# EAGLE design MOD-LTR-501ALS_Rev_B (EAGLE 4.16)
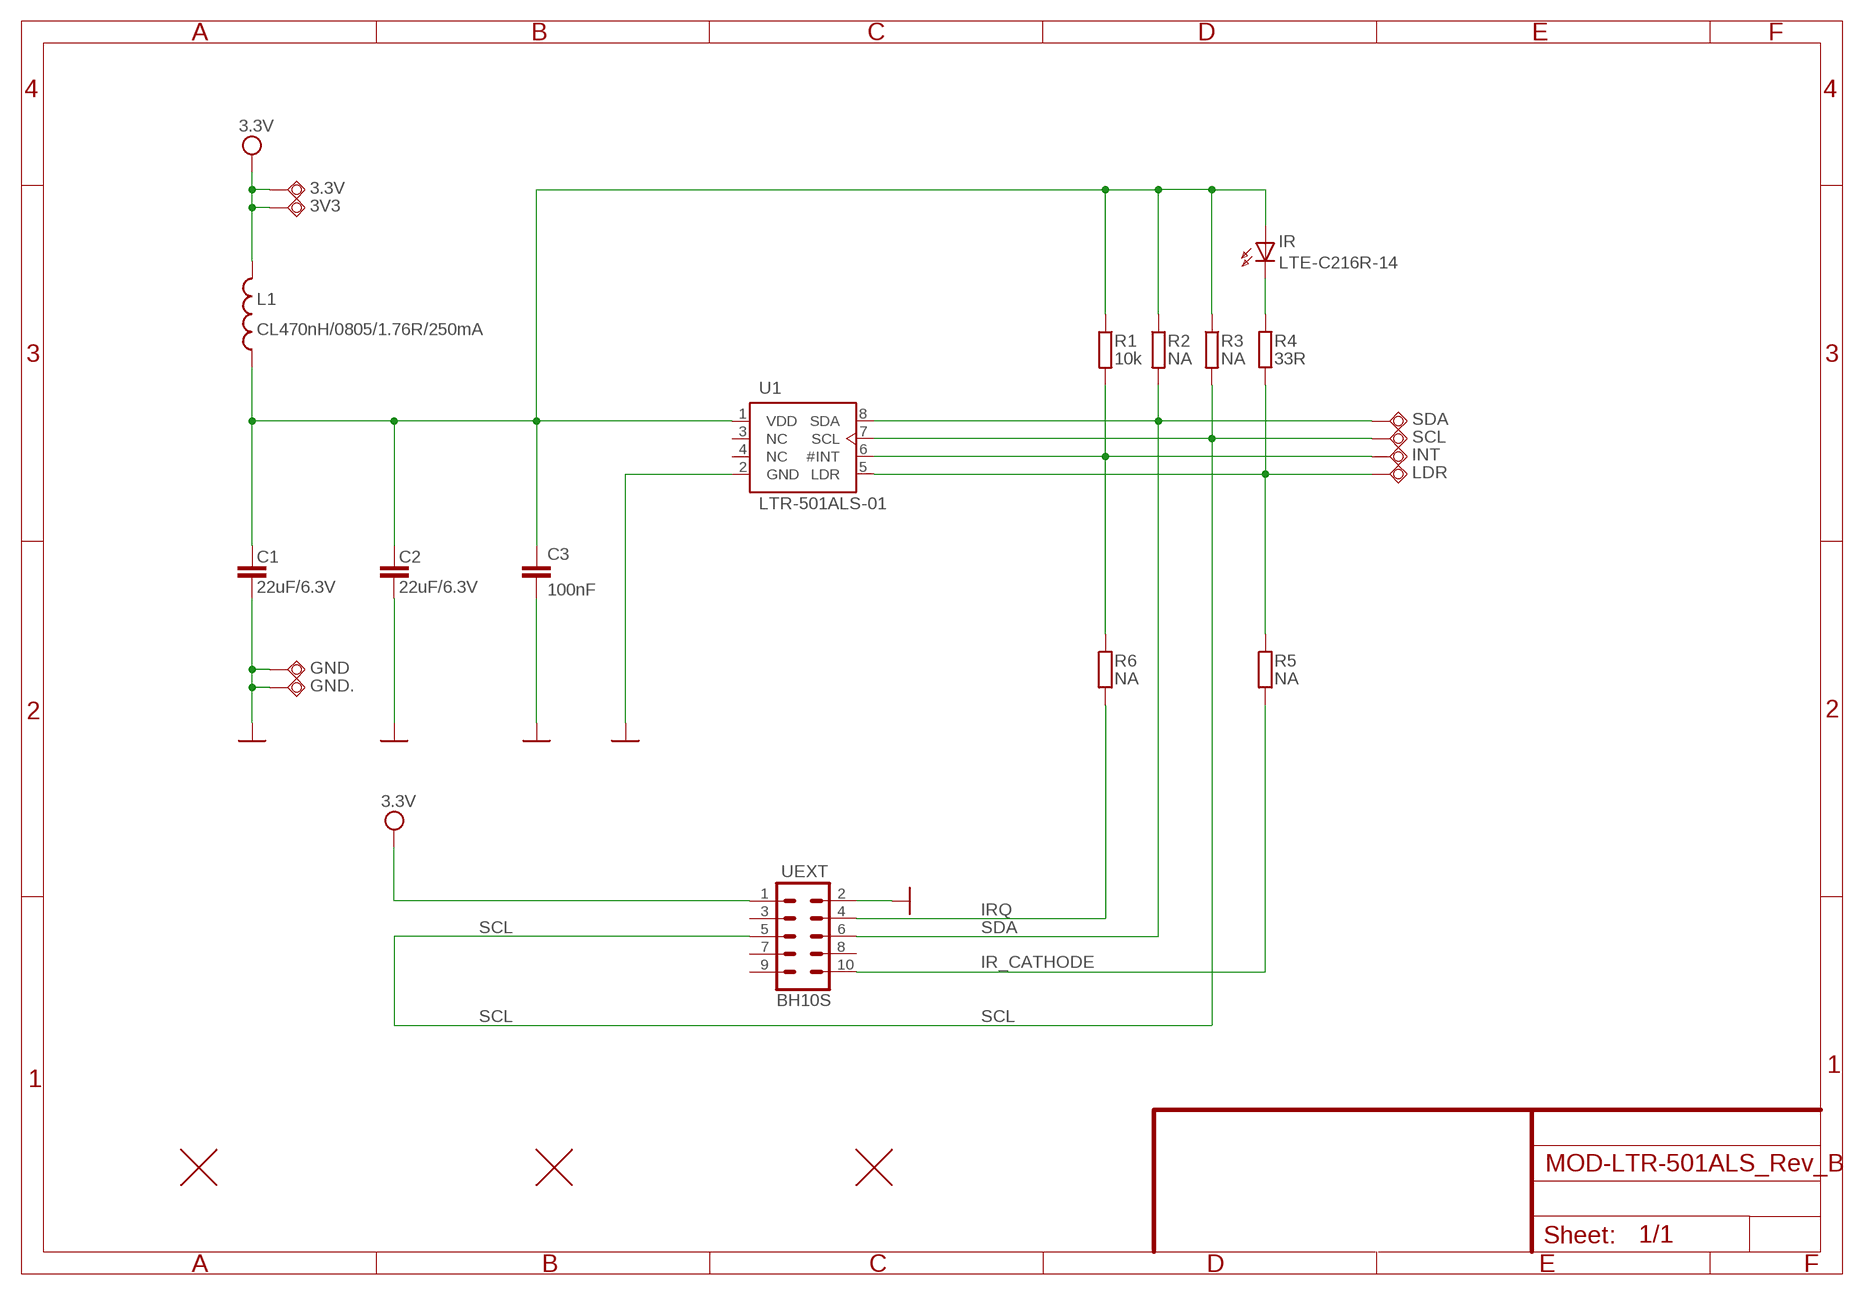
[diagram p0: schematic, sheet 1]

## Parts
3.3V  TESTPAD3  [TEST_PAD40/70/SQUARE]
3V3  TESTPAD3  [TEST_PAD40/70/SQUARE]
C1  22uF/6.3V  C-EUC0603_DWS  [C0603_DWS]
C2  22uF/6.3V  C-EUC0603_DWS  [C0603_DWS]
C3  100nF  C-EUC0603_DWS  [C0603_DWS]
GND  TESTPAD3  [TEST_PAD40/70/SQUARE]
GND.  TESTPAD3  [TEST_PAD40/70/SQUARE]
INT  TESTPAD3  [TEST_PAD40/70/SQUARE]
IR  LTE-C216R-14  LED2  [SMD_LED]
L1  CL470nH/0805/1.76R/250mA  L-USL0805_5MIL_DWS  [L0805_5MIL_DWS]
LDR  TESTPAD3  [TEST_PAD40/70/SQUARE]
R1  10k  R-EU_R0603_5MIL_DWS  [R0603_5MIL_DWS]
R2  NA  R-EU_R0603_5MIL_DWS  [R0603_5MIL_DWS]
R3  NA  R-EU_R0603_5MIL_DWS  [R0603_5MIL_DWS]
R4  33R  R-EU_R0603_5MIL_DWS  [R0603_5MIL_DWS]
R5  NA  R-EU_R0603_5MIL_DWS  [R0603_5MIL_DWS]
R6  NA  R-EU_R0603_5MIL_DWS  [R0603_5MIL_DWS]
SCL  TESTPAD3  [TEST_PAD40/70/SQUARE]
SDA  TESTPAD3  [TEST_PAD40/70/SQUARE]
U1  LTR-501ALS-01  [LTR-501ALS-01]
U$2  FIDUCIAL1X2  [FIDUCIAL-1X2]
U$5  FIDUCIAL1X2  [FIDUCIAL-1X2]
U$6  FIDUCIAL1X2  [FIDUCIAL-1X2]
UEXT  BH10S  ML10SMD  [ML10_PADS]

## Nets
GND [PWR]: C1.2 C2.2 C3.2 GND..P$1(PP) GND.P$1(PP) U1.2(GND) UEXT.2
IR_CATHODE: R5.2 UEXT.10
IRQ: R6.2 UEXT.4
N$1: IR.C R4.2
N$3: INT.P$1(PP) R1.2 R6.1 U1.6(#INT)
N$5: LDR.P$1(PP) R4.1 R5.1 U1.5(LDR)
SCL: R3.2 SCL.P$1(PP) U1.7(SCL) UEXT.5
SDA: R2.2 SDA.P$1(PP) U1.8(SDA) UEXT.6
VCC: 3.3V.P$1(PP) 3V3.P$1(PP) L1.1 UEXT.1 ; supply symbol labelled 3.3V
VDD: C1.1 C2.1 C3.1 IR.A L1.2 R1.1 R2.1 R3.1 U1.1(VDD)
Unconnected: U1.3(NC) U1.4(NC) UEXT.3 UEXT.7 UEXT.8 UEXT.9

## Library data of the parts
3.3V 3V3 GND GND. INT LDR SCL SDA = gogo:TESTPAD: drill 40mils, diameter 70mils
C1-C3 = rcl:C-EU: CAPACITOR, European symbol
IR = DOUBLE-SIDE:LED
L1 = rcl:L-US: INDUCTOR, American symbol
R1-R6 = rcl:R-EU_: RESISTOR, European symbol
U1 = OLIMEX_IC:LTR-501ALS-01: LTR-501ALS-01 2-in-1 Digital Light Sensor and Proximity Sensor
U$2 U$5 U$6 = SparkFunEagle-6-6-07:FIDUCIAL: Fiducial Alignment Points
UEXT = con-harting-ml:ML10: HARTING

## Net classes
0 default: width 0.203 mm, drill 0.178 mm, clearance 0.584 mm
1 PWR: width 0.203 mm, drill 0.178 mm, clearance 0.584 mm

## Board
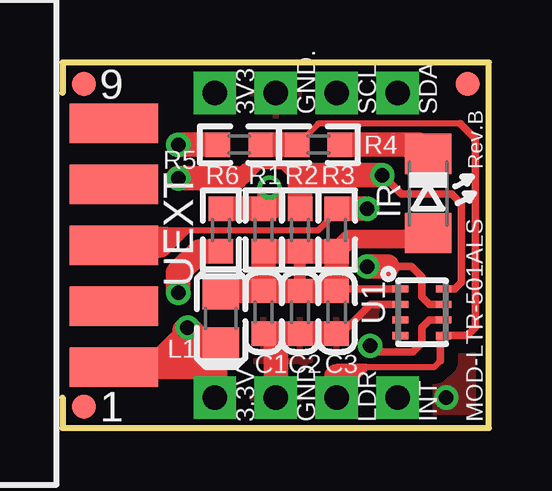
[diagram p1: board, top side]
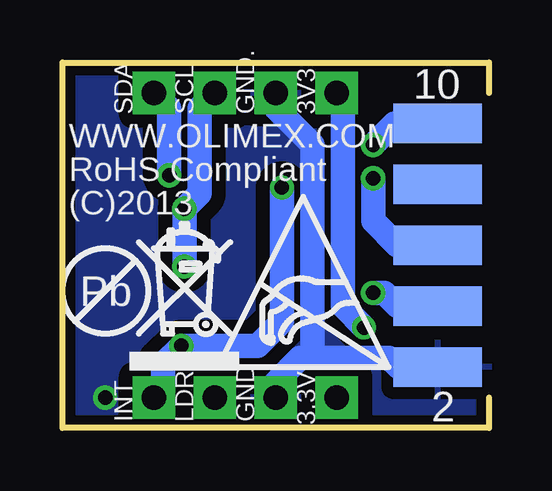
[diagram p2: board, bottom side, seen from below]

Size 17.78 x 15.24 mm. Coordinates in mm from the lower left corner, seen from the top.
Outline: 0,13.97 0,15.24 17.78,15.24 17.78,0 0,0 0,1.27
Copper layers (1+16): Top 0.035mm / dielectric 1.5mm / Bottom 0.035mm
Design rules "default": minimum track width 10mil, minimum drill 23mil, track to track 10mil, track to pad 10mil, pad to pad 10mil, via to via 10mil, smd to smd 1mil, copper to edge 10mil, drill to drill 10mil, minimum pad ring 10mil, minimum via ring 8mil, stop-mask expansion 4mil, vias tented up to drill 25mil, thermal gap 20mil

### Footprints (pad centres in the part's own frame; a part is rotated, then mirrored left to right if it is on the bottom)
TEST_PAD40/70/SQUARE = drill 1.016 pad 1.778 square: P$1 0,0
C0603_DWS = smd 1.016 x 1.016: 1 -0.889,0; 2 0.889,0
SMD_LED = smd 1.676 x 1.93: A 1.65,0; C -1.65,0
L0805_5MIL_DWS = smd 1.27 x 1.524: 1 -1.016,0; 2 1.016,0
R0603_5MIL_DWS = smd 1.016 x 1.016: 1 -0.889,0; 2 0.889,0
LTR-501ALS-01 = smd 0.3 x 0.65: 1 -0.975,-0.9; 2 -0.325,-0.9; 3 0.325,-0.9; 4 0.975,-0.9; 5 0.975,0.9; 6 0.325,0.9; 7 -0.325,0.9; 8 -0.975,0.9
FIDUCIAL-1X2 = smd 1 x 1: 1 0,0
ML10_PADS = smd 1.651 x 3.683: 1 -5.08,-0.229; 3 -2.54,-0.229; 5 0,-0.229; 7 2.54,-0.229; 9 5.08,-0.229 | smd 1.651 x 3.683 bottom: 2 -5.08,-0.229; 4 -2.54,-0.229; 6 0,-0.229; 8 2.54,-0.229; 10 5.08,-0.229

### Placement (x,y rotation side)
3.3V  6.35,1.27 90 top
3V3  6.35,13.97 90 top
C1  8.38,4.83 270 top
C2  9.91,4.83 270 top
C3  11.43,4.83 270 top
GND  8.89,1.27 90 top
GND.  8.89,13.97 90 top
INT  13.97,1.27 0 top
IR  15.24,9.78 270 top
L1  6.6,4.57 90 top
LDR  11.43,1.27 0 top
R1  8.38,8.26 90 top
R2  9.91,8.26 90 top
R3  11.43,8.26 90 top
R4  10.67,11.81 0 top
R5  7.37,11.81 180 top
R6  6.6,8.26 270 top
SCL  11.43,13.97 0 top
SDA  13.97,13.97 0 top
U1  14.99,4.83 270 top
U$1  [ESD_SYMBOL]  11.3,2.54 0 bottom
U$2  0.89,14.35 0 top
U$3  [PB_SMALL]  16,5.71 0 bottom
U$4  [RECYCLE_BIN1/8]  14.99,2.41 0 bottom
U$5  0.89,0.89 0 top
U$6  16.89,14.35 0 top
UEXT  1.91,7.62 90 top

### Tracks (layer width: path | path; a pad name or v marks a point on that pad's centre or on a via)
GND  (via drill 0.6)
  Top 0.305: C3.2 11.63,3.94 12.85,5.15 U1.2
  Top 1.016: C3.2 C2.2 8.89,3.94 | GND.P$1 8.89,3.94 | 8.89,3.94 C1.2
  Bottom 1.016: UEXT.2 3.79,2.54 4.17,2.92 7.37,2.92 | 7.37,2.92 7.87,2.92 8.89,1.91 GND.P$1 | GND..P$1 8.89,13.34 7.37,11.81 7.37,2.92
  other vias: 16,1.27
  pour Bottom (isolate 0.406): 0,16.51 0,-1.27 19.05,-1.27 19.05,16.51
  pour Top (isolate 0.406): -1.27,17.78 -1.27,-2.54 20.32,-2.54 20.32,17.78
IR_CATHODE  (via drill 0.6)
  Top 1.016: v4.83,11.81 R5.2
  Bottom 1.016: UEXT.10 3.94,12.7 v4.83,11.81
IRQ  (via drill 0.6)
  Top 1.016: v4.83,5.64 4.83,6.48 5.71,7.37 R6.2
  Bottom 1.016: UEXT.4 3.81,5.08 4.37,5.64 v4.83,5.64
N$1
  Top 1.016: R4.2 14.86,11.81 IR.C
N$3  (via drill 0.6)
  Top 0.305: U1.6 15.3,4.5 14.99,4.19 14.99,3.56 14.61,3.17 13.08,3.17 v12.83,3.43
  Top 1.016: R6.1 R1.2 8.64,9.14 v8.64,10.03
  Bottom 1.016: INT.P$1 13.59,1.27 13.59,2.67 v12.83,3.43 9.65,3.43 8.64,4.45 v8.64,10.03
N$5
  Top 0.254: R4.1 10.67,12.7 16.59,12.7 | 11.43,2.16 11.43,2.54 12.19,2.54 | 12.45,2.54 12.19,2.54 | 12.7,2.54 12.45,2.54 | 12.7,2.54 15.49,2.54 15.75,2.79 | 11.43,1.78 12.19,2.54 | 11.43,1.52 12.45,2.54 | LDR.P$1 12.7,2.54
  Top 0.305: 15.75,2.79 15.75,3.85 U1.5 16.88,3.85 17.22,4.19 17.22,12.06 16.59,12.7
  Top 1.016: R4.1 R5.1 | LDR.P$1 11.43,1.52 11.43,1.78 11.43,2.16
SCL  (via drill 0.6)
  Top 0.254: 4.32,7.87 4.32,8.26 4.95,8.26 | 4.95,8.26 5.23,8.26 | 5.23,8.26 10.67,8.26 11.43,9.02 R3.2 | 4.95,8.26 4.57,7.87 | 5.23,8.26 4.6,7.62
  Top 0.305: 13.54,6.73 14.55,6.73 14.99,6.3 14.99,5.46 15.3,5.15 U1.7
  Top 1.016: UEXT.5 3.43,7.62 | 3.43,7.62 3.68,7.87 4.32,7.87 4.06,7.62 3.43,7.62 | R3.2 v12.7,9.14 | v12.7,6.73 13.54,6.73
  Bottom 1.016: v12.7,6.73 v12.7,9.14 12.06,9.78 12.06,13.34 SCL.P$1
SDA  (via drill 0.6)
  Top 0.254: 7.21,10.41 7.21,10.54 7.59,10.92 7.95,10.92 | 7.95,10.92 8.26,10.92 | 8.26,10.92 9.14,10.92 | 9.14,10.92 9.4,10.92 | 9.4,10.92 9.91,10.92 9.91,10.54 | 9.4,10.92 9.91,10.41 | 9.14,10.92 9.91,10.16 | 7.95,10.92 7.44,10.41 | 8.26,10.92 7.62,10.29
  Top 0.305: U1.8 16.37,5.8 16.64,6.07 16.64,9.35 16.23,9.75 14.12,9.75 v13.34,10.54
  Top 1.016: v4.83,10.41 7.21,10.41 | R2.2 9.91,10.16 9.91,10.41 9.91,10.54 v13.34,10.54
  Bottom 1.016: UEXT.6 3.81,7.62 4.83,8.64 v4.83,10.41 | v13.34,10.54 13.34,13.34 SDA.P$1
VCC  (via drill 0.6)
  Top 1.016: UEXT.1 3.81,2.54 | 3.81,2.54 5.08,2.54 | 5.08,2.54 6.35,2.54 | 6.35,2.54 3.3V.P$1 | 6.35,2.54 6.35,3.56 | 6.35,3.56 L1.1 | 5.08,3.56 5.84,3.56 | 6.35,3.56 5.84,3.56 | 5.08,2.54 5.08,3.56 | 5.08,3.56 5.08,4.06 v5.21,4.19 5.84,3.56 | 3.81,2.54 4.83,3.56 5.08,3.56
  Bottom 1.016: v5.21,4.19 6.1,5.08 6.1,13.97 3V3.P$1
VDD
  Top 0.305: 11.43,5.8 U1.1
  Top 0.508: C2.1 R2.1
  Top 0.762: IR.A 15.24,7.87 11.94,7.87 R3.1
  Top 1.016: L1.2 6.6,5.71 C1.1 | C1.1 C2.1 C3.1 11.43,5.8 R3.1 R2.1 R1.1 C1.1

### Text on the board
tNames: Rev.B | MOD-LTR-501ALS
bNames: WWW.OLIMEX.COM | RoHS Compliant | (C)2013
